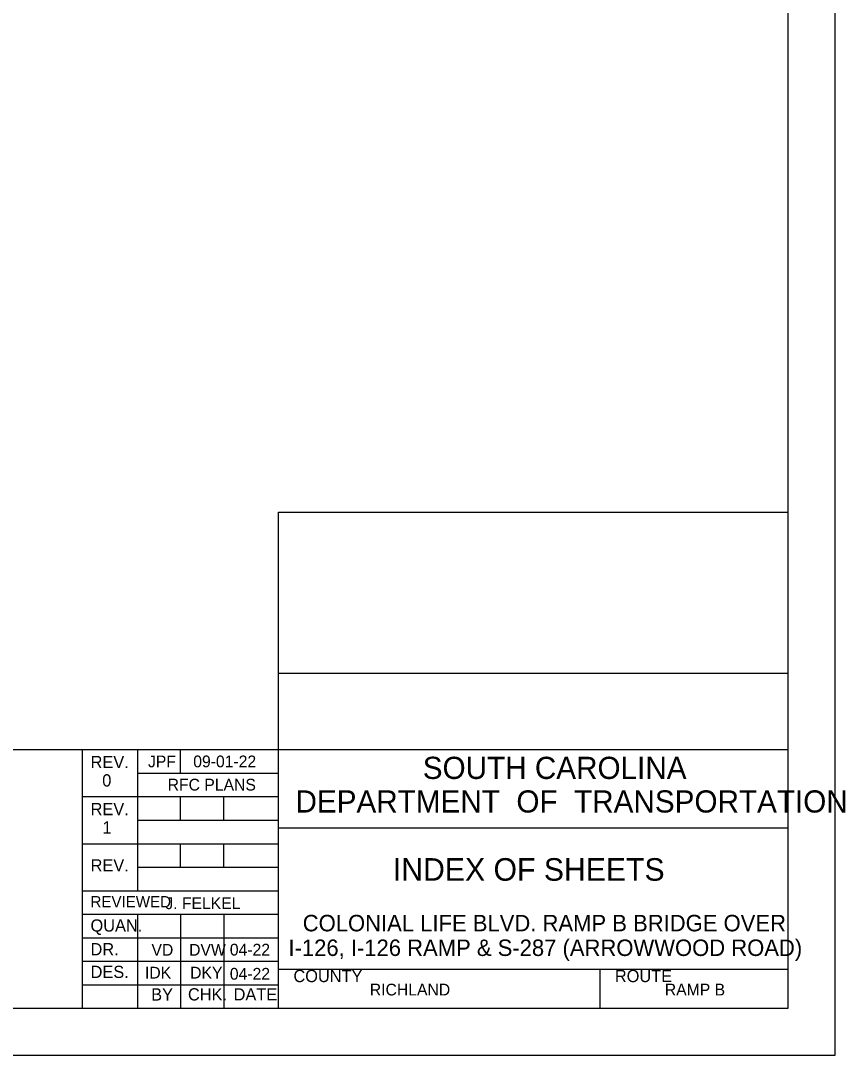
# Model space of a CAD drawing. Extents: x -125.5 to -89.4, y -5.1 to 16.9.
# Drawn here: x -98.19 to -89.43, y -5.07 to 5.93 of the extents above; entities that cross this region are included whole.
import ezdxf

# ---------------------------------------------------------------- set-up
doc = ezdxf.new("R2010")
doc.units = 0
for name, color, linetype in [('BR_BORDER LINES', 7, 'Continuous'), ('BR_TEXT', 7, 'Continuous'), ('Level 31', 7, 'Continuous')]:
    doc.layers.add(name, color=color, linetype=linetype)

msp = doc.modelspace()

# ---------------------------------------------------------------- linework, layer by layer
at = {"layer": 'BR_BORDER LINES'}
for p, q in [((-90.033, -4.566), (-90.033, 16.434)), ((-95.45, -4.566), (-95.45, 0.71)), ((-95.45, 0.71), (-90.033, 0.71)), ((-95.45, -1.004), (-90.033, -1.004)), ((-102.899, -1.816), (-97.534, -1.816)), ((-97.534, -4.566), (-97.534, -1.816)), ((-97.534, -1.816), (-90.033, -1.816)), ((-96.95, -1.816), (-96.95, -3.316)), ((-96.492, -2.066), (-96.492, -1.816)), ((-96.95, -2.066), (-95.45, -2.066)), ((-97.534, -2.316), (-95.45, -2.316)), ((-96.492, -2.566), (-96.492, -2.316)), ((-96.034, -2.566), (-96.034, -2.316)), ((-96.95, -2.566), (-95.45, -2.566)), ((-95.45, -2.649), (-95.45, -2.649)), ((-95.45, -2.649), (-90.033, -2.649)), ((-97.534, -2.816), (-95.45, -2.816)), ((-96.492, -3.066), (-96.492, -2.816)), ((-96.034, -3.066), (-96.034, -2.816)), ((-96.95, -3.066), (-95.45, -3.066)), ((-97.534, -3.316), (-95.45, -3.316)), ((-97.534, -3.566), (-95.45, -3.566)), ((-96.95, -3.566), (-96.95, -4.566)), ((-96.492, -3.566), (-96.492, -4.566)), ((-96.034, -3.566), (-96.034, -4.566)), ((-97.534, -3.816), (-95.45, -3.816)), ((-97.534, -4.066), (-95.45, -4.066)), ((-95.45, -4.149), (-90.033, -4.149)), ((-95.353, -4.149), (-90.033, -4.149)), ((-92.033, -4.566), (-92.033, -4.149)), ((-97.534, -4.316), (-95.45, -4.316)), ((-123.699, -4.566), (-90.033, -4.566))]:
    msp.add_line(p, q, dxfattribs=at)
at = {"layer": 'Level 31'}
msp.add_line((-92.742, -3.09), (-92.742, -3.09), dxfattribs=at)
msp.add_lwpolyline([(-125.533, -5.066), (-89.533, -5.066), (-89.533, 16.934), (-125.533, 16.934)], close=True, dxfattribs=at)

# ---------------------------------------------------------------- texts
at = {"layer": 'BR_TEXT'}
for s, height, p in [('REV.', 0.13, (-97.449, -2.013)), ('JPF', 0.125, (-96.839, -2.004)), ('09-01-22', 0.125, (-96.358, -2.004)), ('SOUTH CAROLINA', 0.23587, (-93.918, -2.128)), ('0', 0.13, (-97.325, -2.208)), ('RFC PLANS', 0.125, (-96.63, -2.251)), ('DEPARTMENT  OF  TRANSPORTATION', 0.23587, (-95.271, -2.485)), ('REV.', 0.13, (-97.449, -2.513)), ('1', 0.13, (-97.323, -2.708)), ('INDEX OF SHEETS', 0.24, (-94.236, -3.21)), ('REV.', 0.13, (-97.449, -3.111)), ('REVIEWED', 0.12, (-97.45, -3.493)), ('J. FELKEL', 0.125, (-96.655, -3.512)), ('QUAN.', 0.13, (-97.45, -3.751)), ('COLONIAL LIFE BLVD. RAMP B BRIDGE OVER', 0.175, (-95.194, -3.748)), ('I-126, I-126 RAMP & S-287 (ARROWWOOD ROAD) ', 0.175, (-95.346, -4.01)), ('DR.', 0.13, (-97.45, -4.003)), ('VD', 0.125, (-96.802, -4.007)), ('DVW', 0.125, (-96.402, -4.007)), ('04-22', 0.125, (-95.969, -4.005)), ('DES.', 0.13, (-97.449, -4.244)), ('IDK', 0.125, (-96.871, -4.25)), ('DKY', 0.125, (-96.391, -4.25)), ('04-22', 0.125, (-95.969, -4.262)), ('COUNTY', 0.13, (-95.293, -4.288)), ('ROUTE', 0.13, (-91.876, -4.288)), ('BY', 0.13, (-96.805, -4.484)), ('CHK.', 0.13, (-96.414, -4.483)), ('DATE', 0.13, (-95.929, -4.483)), ('RICHLAND', 0.125, (-94.481, -4.43)), ('RAMP B', 0.125, (-91.345, -4.43))]:
    msp.add_text(s, height=height, dxfattribs=at).set_placement(p)

doc.saveas('drawing.dxf')
